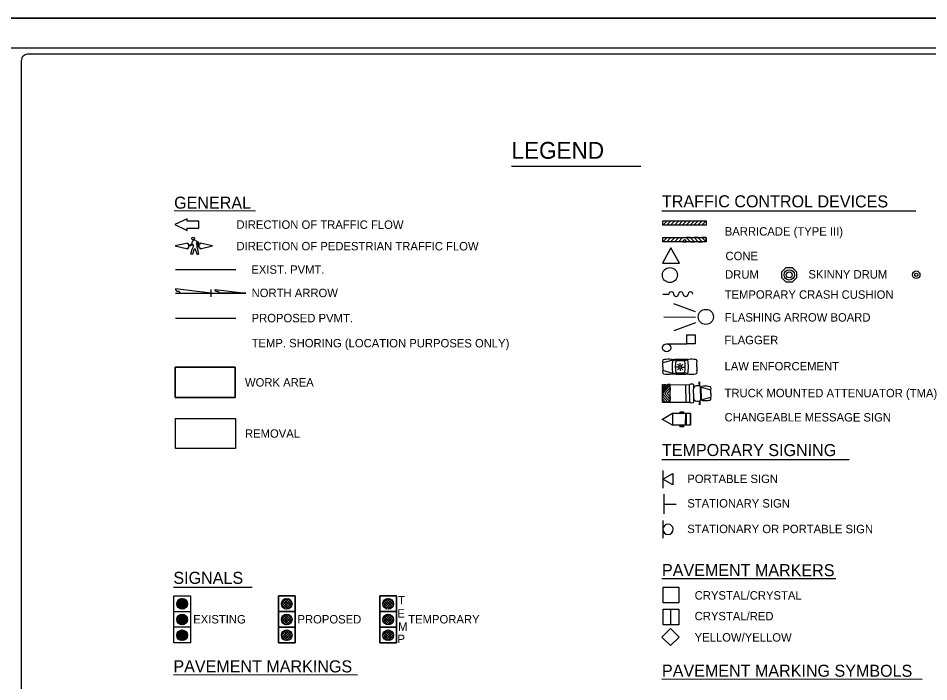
# Model space of a CAD drawing. Extents: x 198 to 2213, y -571 to 529.
# Drawn here: x 931 to 1688, y -22 to 529 of the extents above; entities that cross this region are included whole.
import ezdxf

# ---------------------------------------------------------------- set-up
doc = ezdxf.new("R2010")
doc.units = 0
for name, color, linetype in [('P_RDY_Dimension_Text', 7, 'Continuous'), ('Prop Shade Light', 7, 'Continuous'), ('Sheet Data Field CELL', 7, 'Continuous'), ('Sheet PE Seal CELL', 7, 'Continuous'), ('Sheet_Title_Block_Text', 7, 'Continuous'), ('Text', 7, 'Continuous')]:
    doc.layers.add(name, color=color, linetype=linetype)

msp = doc.modelspace()

# ---------------------------------------------------------------- linework, layer by layer
at = {"layer": 'P_RDY_Dimension_Text'}
for points in [[(1061.06, 214.03), (1111.06, 214.03), (1111.06, 239.03), (1061.06, 239.03)], [(1146.95, 49.25), (1160.75, 49.25), (1160.75, 9.95), (1146.95, 9.95)], [(1231.3, 49.25), (1245.1, 49.25), (1245.1, 9.95), (1231.3, 9.95)]]:
    msp.add_lwpolyline(points, close=True, dxfattribs=at)
at = {"layer": 'Prop Shade Light'}
for p, q in [((1072.69, 340.35), (1075.18, 341.98)), ((1075.18, 341.98), (1075.34, 342.96)), ((1076.14, 341.27), (1075.36, 340.55)), ((1077.97, 344.5), (1080.47, 343.01)), ((1079.56, 342.36), (1078.75, 342.52)), ((1079.78, 339.54), (1079.56, 342.36)), ((1080.47, 343.01), (1080.5, 339.54)), ((1073.08, 339.8), (1072.69, 340.35)), ((1075.36, 340.55), (1073.08, 339.8)), ((1074.18, 333.09), (1075.25, 337.14)), ((1075.51, 332.67), (1074.18, 333.09)), ((1075.25, 337.14), (1076.48, 339.41)), ((1076.67, 336.59), (1075.51, 332.67)), ((1077.65, 337.56), (1076.67, 336.59)), ((1079.62, 332.38), (1077.65, 337.56)), ((1079.31, 338.46), (1080.59, 333.06)), ((1080.59, 333.06), (1079.62, 332.38)), ((1080.5, 339.54), (1079.78, 339.54))]:
    msp.add_line(p, q, dxfattribs=at)
for centre, radius, start, end in [((1078.51, 342.44), 3.22, 140.16781, 170.55558), ((1076.69, 343.96), 0.84, 96.88059, 140.16781), ((1071.07, 339.38), 5.41, 0.28805, 20.36723), ((1076.85, 342.62), 2.19, 59.1458, 96.8806), ((1071.07, 339.38), 8.29, 353.63563, 22.23387)]:
    msp.add_arc(centre, radius, start, end, dxfattribs=at)
at = {"layer": 'Sheet Data Field CELL'}
for points in [[(197.66, -570.86), (1885.65, -570.86), (1885.65, 529.13), (197.66, 529.13)], [(197.66, 529.13), (1885.65, 529.13), (1885.65, -570.86), (197.66, -570.86)]]:
    msp.add_lwpolyline(points, close=True, dxfattribs=at)
at = {"layer": 'Sheet PE Seal CELL'}
for p, q in [((1850.37, 504.14), (370.94, 504.14)), ((933.13, 493.85), (933.13, -535.58)), ((1850.37, 499.14), (938.42, 499.14)), ((1340.7, 406.25), (1448.09, 406.18)), ((1060.26, 369.22), (1127.86, 369.17)), ((1465.78, 369.17), (1676.67, 369.02)), ((1071.18, 362.49), (1060.84, 357.63)), ((1060.84, 357.63), (1071.18, 352.75)), ((1071.18, 360.52), (1071.18, 362.49)), ((1080.78, 360.51), (1071.18, 360.52)), ((1080.78, 354.71), (1080.78, 360.51)), ((1466.45, 357.11), (1466.45, 360.71)), ((1466.45, 360.71), (1469.99, 360.71)), ((1469.99, 360.71), (1466.45, 357.11)), ((1466.45, 360.71), (1502.43, 360.71)), ((1466.45, 357.17), (1466.45, 360.71)), ((1502.43, 357.17), (1466.45, 357.17)), ((1469.69, 357.11), (1473.23, 360.71)), ((1472.92, 357.11), (1469.69, 357.11)), ((1476.47, 360.71), (1472.92, 357.11)), ((1473.23, 360.71), (1476.47, 360.71)), ((1476.16, 357.11), (1479.71, 360.71)), ((1479.4, 357.11), (1476.16, 357.11)), ((1482.94, 360.71), (1479.4, 357.11)), ((1479.71, 360.71), (1482.94, 360.71)), ((1482.64, 357.11), (1486.18, 360.71)), ((1485.88, 357.11), (1482.64, 357.11)), ((1489.42, 360.71), (1485.88, 357.11)), ((1486.18, 360.71), (1489.42, 360.71)), ((1489.11, 357.11), (1492.72, 360.71)), ((1492.35, 357.11), (1489.11, 357.11)), ((1495.95, 360.71), (1492.35, 357.11)), ((1492.72, 360.71), (1495.95, 360.71)), ((1495.59, 357.11), (1499.19, 360.71)), ((1498.83, 357.11), (1495.59, 357.11)), ((1502.43, 360.71), (1498.83, 357.11)), ((1499.19, 360.71), (1502.43, 360.71)), ((1502.43, 360.71), (1502.43, 357.17)), ((1071.18, 352.75), (1071.18, 354.72)), ((1071.18, 354.72), (1080.78, 354.71)), ((1071.52, 342.32), (1061.17, 339.89)), ((1071.51, 341.33), (1071.52, 342.32)), ((1072.44, 341.33), (1071.51, 341.33)), ((1072.44, 338.43), (1072.44, 341.33)), ((1081.79, 341.33), (1080.86, 341.33)), ((1080.86, 341.33), (1080.86, 338.43)), ((1092.13, 339.87), (1081.79, 342.31)), ((1081.79, 342.31), (1081.79, 341.33)), ((1466.46, 343.4), (1466.46, 347)), ((1466.46, 347), (1470, 347)), ((1470, 347), (1466.46, 343.4)), ((1466.46, 347), (1502.43, 347)), ((1466.46, 343.4), (1466.46, 347)), ((1502.43, 343.4), (1466.46, 343.4)), ((1469.69, 343.4), (1473.24, 347)), ((1472.93, 343.4), (1469.69, 343.4)), ((1476.47, 347), (1472.93, 343.4)), ((1473.24, 347), (1476.47, 347)), ((1476.17, 343.4), (1479.71, 347)), ((1479.4, 343.4), (1476.17, 343.4)), ((1482.95, 347), (1479.4, 343.4)), ((1479.71, 347), (1482.95, 347)), ((1482.64, 343.4), (1484.44, 345.23)), ((1485.88, 343.4), (1482.64, 343.4)), ((1483.01, 343.4), (1486.24, 343.4)), ((1484.44, 345.23), (1486.24, 343.4)), ((1489.18, 347), (1485.94, 347)), ((1485.94, 347), (1489.48, 343.4)), ((1492.72, 343.4), (1489.18, 347)), ((1489.48, 343.4), (1492.72, 343.4)), ((1495.65, 347), (1492.41, 347)), ((1492.41, 347), (1495.96, 343.4)), ((1499.19, 343.4), (1495.65, 347)), ((1495.96, 343.4), (1499.19, 343.4)), ((1502.43, 347), (1498.89, 347)), ((1498.89, 347), (1502.43, 343.4)), ((1502.43, 347), (1502.43, 343.4)), ((1502.43, 343.4), (1502.43, 347)), ((1061.17, 339.89), (1071.51, 337.45)), ((1071.51, 337.45), (1071.51, 338.43)), ((1071.51, 338.43), (1072.44, 338.43)), ((1080.86, 338.43), (1081.79, 338.43)), ((1081.79, 337.44), (1092.13, 339.87)), ((1081.79, 338.43), (1081.79, 337.44)), ((1061.47, 320.32), (1111.67, 320.29)), ((1090.7, 300.62), (1061.48, 304.21)), ((1090.7, 303.75), (1090.7, 297.49)), ((1094.42, 303.75), (1119.92, 300.62)), ((1061.48, 300.62), (1119.92, 300.62)), ((1064.93, 300.63), (1090.7, 300.62)), ((1119.92, 300.62), (1097.73, 300.62)), ((1466.5, 299.89), (1471.5, 299.89)), ((1493.75, 285.17), (1475.71, 291.75)), ((1493.75, 280.56), (1467.2, 280.58)), ((1061.47, 280.01), (1111.66, 279.97)), ((1493.74, 275.95), (1475.69, 269.4)), ((1469.67, 258.67), (1486.35, 258.66)), ((1474.76, 244.96), (1466.54, 242.71)), ((1466.54, 239.5), (1466.54, 242.71)), ((1474.76, 244.96), (1477.3, 244.41)), ((1480.9, 240.58), (1480.9, 242.6)), ((1487.18, 244.95), (1484.63, 244.4)), ((1486.45, 245.1), (1486.45, 244.79)), ((1494.64, 239.48), (1494.64, 242.69)), ((1466.54, 239.5), (1466.53, 236.27)), ((1474.75, 234.02), (1466.53, 236.27)), ((1479.6, 239.29), (1477.58, 239.3)), ((1479.98, 240.21), (1478.55, 241.63)), ((1479.97, 238.38), (1478.55, 236.95)), ((1480.89, 238), (1480.89, 235.98)), ((1481.8, 238.37), (1483.23, 236.94)), ((1481.81, 240.2), (1483.24, 241.63)), ((1482.19, 239.28), (1484.2, 239.28)), ((1494.64, 239.48), (1494.64, 236.25)), ((1474.75, 234.02), (1477.3, 234.57)), ((1487.17, 234.01), (1484.63, 234.56)), ((1486.44, 234.18), (1486.44, 233.88)), ((1486.44, 234.18), (1486.44, 233.88)), ((1466.16, 210.07), (1466.17, 224.62)), ((1472.62, 224.62), (1466.16, 217.35)), ((1466.16, 217.35), (1466.17, 219.6)), ((1466.17, 224.62), (1488.67, 224.6)), ((1466.17, 224.62), (1466.17, 221.84)), ((1466.17, 224.62), (1468.64, 224.62)), ((1468.64, 224.62), (1466.17, 221.84)), ((1466.17, 219.6), (1470.67, 224.62)), ((1468.19, 217.34), (1472.62, 222.37)), ((1472.62, 220.12), (1470.14, 217.34)), ((1470.67, 224.62), (1472.62, 224.62)), ((1472.61, 210.07), (1472.62, 224.62)), ((1472.62, 222.37), (1472.62, 220.12)), ((1485.59, 217.33), (1485.59, 224.61)), ((1488.66, 217.33), (1488.67, 224.6)), ((1492.11, 217.33), (1492.12, 224.6)), ((1496.77, 225.05), (1496.77, 226.85)), ((1497.07, 223.32), (1497.07, 226.85)), ((1497.29, 223.32), (1497.3, 226.85)), ((1497.89, 217.32), (1497.89, 222.57)), ((1498.41, 217.32), (1498.42, 222.57)), ((1498.42, 222.57), (1506.29, 220.39)), ((1506.29, 217.32), (1506.29, 220.39)), ((1466.16, 217.35), (1472.61, 210.07)), ((1466.16, 215.17), (1466.16, 217.35)), ((1470.66, 210.07), (1466.16, 215.17)), ((1466.16, 212.85), (1466.16, 210.07)), ((1468.63, 210.07), (1466.16, 212.85)), ((1472.61, 212.39), (1468.19, 217.34)), ((1470.21, 217.34), (1472.61, 214.64)), ((1472.61, 214.64), (1472.61, 212.39)), ((1485.59, 217.33), (1485.58, 210.06)), ((1488.66, 217.33), (1488.66, 210.05)), ((1492.11, 217.33), (1492.11, 210.05)), ((1497.89, 217.32), (1497.89, 212.07)), ((1498.41, 217.32), (1498.41, 212.07)), ((1498.41, 212.07), (1506.29, 214.24)), ((1506.29, 217.32), (1506.29, 214.24)), ((1466.16, 210.07), (1488.66, 210.05)), ((1466.16, 210.07), (1468.63, 210.07)), ((1472.61, 210.07), (1470.66, 210.07)), ((1496.76, 209.6), (1496.76, 207.87)), ((1497.06, 211.32), (1497.06, 207.87)), ((1497.29, 211.32), (1497.28, 207.87)), ((1474.48, 200.61), (1466.07, 195.76)), ((1474.48, 200.61), (1474.47, 190.91)), ((1489.5, 200.6), (1474.48, 200.61)), ((1483.83, 201.68), (1480.73, 201.68)), ((1483.83, 200.8), (1480.73, 200.8)), ((1485.19, 200.61), (1485.18, 190.9)), ((1485.99, 200.61), (1485.99, 190.9)), ((1489.5, 200.61), (1489.5, 190.9)), ((1489.5, 190.89), (1489.5, 200.6)), ((1474.47, 190.91), (1466.07, 195.76)), ((1489.5, 190.9), (1474.47, 190.91)), ((1483.82, 190.59), (1480.72, 190.6)), ((1483.82, 189.67), (1480.72, 189.68)), ((1465.78, 162.49), (1621.46, 162.38)), ((1466.57, 153.39), (1466.56, 138.54)), ((1466.56, 146.11), (1474.67, 150.76)), ((1474.66, 141.46), (1466.56, 146.11)), ((1474.67, 150.76), (1474.66, 141.46)), ((1467.19, 133.53), (1467.18, 117.33)), ((1467.18, 125.36), (1477.68, 125.35)), ((1466.56, 111.78), (1466.55, 96.93)), ((1465.78, 63.61), (1610.16, 63.51)), ((1059.64, 56.26), (1125.23, 56.21)), ((1149.45, 42.65), (1153.75, 46.95)), ((1149.8, 40.85), (1155.55, 46.65)), ((1150.6, 39.55), (1156.85, 45.8)), ((1157.5, 40.05), (1151.35, 46.2)), ((1158.15, 41.5), (1152.8, 46.85)), ((1158.1, 43.65), (1155, 46.8)), ((1233.8, 42.65), (1238.1, 46.95)), ((1234.15, 40.85), (1239.9, 46.65)), ((1234.95, 39.55), (1241.2, 45.8)), ((1241.85, 40.05), (1235.7, 46.2)), ((1242.5, 41.5), (1237.15, 46.85)), ((1242.45, 43.65), (1239.35, 46.8)), ((1152.95, 38.2), (1149.55, 41.65)), ((1155, 38.3), (1149.6, 43.7)), ((1156.45, 39), (1150.3, 45.1)), ((1151.8, 38.65), (1157.75, 44.55)), ((1153.45, 38.2), (1158.25, 42.95)), ((1156.35, 38.95), (1157.6, 40.2)), ((1237.3, 38.2), (1233.9, 41.65)), ((1239.35, 38.3), (1233.95, 43.7)), ((1240.8, 39), (1234.65, 45.1)), ((1236.15, 38.65), (1242.1, 44.55)), ((1237.8, 38.2), (1242.6, 42.95)), ((1240.7, 38.95), (1241.95, 40.2)), ((1149.45, 29.55), (1153.75, 33.85)), ((1155, 25.2), (1149.6, 30.6)), ((1149.8, 27.75), (1155.55, 33.55)), ((1156.45, 25.9), (1150.3, 32)), ((1150.6, 26.45), (1156.85, 32.7)), ((1157.5, 26.95), (1151.35, 33.1)), ((1151.8, 25.55), (1157.75, 31.45)), ((1158.15, 28.4), (1152.8, 33.75)), ((1158.1, 30.55), (1155, 33.7)), ((1233.8, 29.55), (1238.1, 33.85)), ((1239.35, 25.2), (1233.95, 30.6)), ((1234.15, 27.75), (1239.9, 33.55)), ((1240.8, 25.9), (1234.65, 32)), ((1234.95, 26.45), (1241.2, 32.7)), ((1241.85, 26.95), (1235.7, 33.1)), ((1236.15, 25.55), (1242.1, 31.45)), ((1242.5, 28.4), (1237.15, 33.75)), ((1242.45, 30.55), (1239.35, 33.7)), ((1152.95, 25.1), (1149.55, 28.55)), ((1153.45, 25.1), (1158.25, 29.85)), ((1156.35, 25.85), (1157.6, 27.1)), ((1237.3, 25.1), (1233.9, 28.55)), ((1237.8, 25.1), (1242.6, 29.85)), ((1240.7, 25.85), (1241.95, 27.1)), ((1149.45, 16.45), (1153.75, 20.75)), ((1152.95, 12), (1149.55, 15.45)), ((1155, 12.1), (1149.6, 17.5)), ((1149.8, 14.65), (1155.55, 20.45)), ((1156.45, 12.8), (1150.3, 18.9)), ((1150.6, 13.35), (1156.85, 19.6)), ((1157.5, 13.85), (1151.35, 20)), ((1151.8, 12.45), (1157.75, 18.35)), ((1158.15, 15.3), (1152.8, 20.65)), ((1153.45, 12), (1158.25, 16.75)), ((1158.1, 17.45), (1155, 20.6)), ((1233.8, 16.45), (1238.1, 20.75)), ((1237.3, 12), (1233.9, 15.45)), ((1239.35, 12.1), (1233.95, 17.5)), ((1234.15, 14.65), (1239.9, 20.45)), ((1240.8, 12.8), (1234.65, 18.9)), ((1234.95, 13.35), (1241.2, 19.6)), ((1241.85, 13.85), (1235.7, 20)), ((1236.15, 12.45), (1242.1, 18.35)), ((1242.5, 15.3), (1237.15, 20.65)), ((1237.8, 12), (1242.6, 16.75)), ((1242.45, 17.45), (1239.35, 20.6)), ((1156.35, 12.75), (1157.6, 14)), ((1240.7, 12.75), (1241.95, 14)), ((1059.64, -16.29), (1212.69, -16.4)), ((1465.78, -19.92), (1681.97, -20.08))]:
    msp.add_line(p, q, dxfattribs=at)
for points in [[(1473.2, 338.44), (1466.21, 325.48), (1480.3, 325.53)], [(1565.54, 313.37), (1565.54, 318.35), (1569.06, 321.88), (1574.04, 321.86), (1577.55, 318.34), (1577.55, 313.36), (1574.03, 309.83), (1569.05, 309.85)], [(1486.35, 258.66), (1486.36, 265.92), (1493.32, 265.91), (1493.31, 258.65)], [(1111.06, 239.03), (1061.06, 239.03), (1061.06, 214.03), (1111.06, 214.03)], [(1061.06, 239.03), (1111.06, 239.03), (1111.06, 214.03), (1061.06, 214.03)], [(1470.67, 224.62), (1466.17, 219.6), (1466.16, 215.17), (1470.66, 210.07), (1472.61, 210.07), (1466.16, 217.35), (1472.62, 224.62)], [(1466.17, 221.84), (1466.17, 224.62), (1468.64, 224.62)], [(1472.61, 212.39), (1468.19, 217.34), (1472.62, 222.37), (1472.62, 220.12), (1470.21, 217.34), (1472.61, 214.64)], [(1466.16, 212.85), (1468.63, 210.07), (1466.16, 210.07)], [(1061.28, 196.52), (1111.28, 196.52), (1111.28, 171.52), (1061.28, 171.52)], [(1061.28, 196.52), (1111.28, 196.52), (1111.28, 171.52), (1061.28, 171.52)], [(1061.28, 196.52), (1111.28, 196.52), (1111.28, 171.52), (1061.28, 171.52)], [(1146.95, 36.15), (1160.75, 36.15), (1160.75, 49.25), (1146.95, 49.25)], [(1231.3, 36.15), (1245.1, 36.15), (1245.1, 49.25), (1231.3, 49.25)], [(1473.14, 38.15), (1479.65, 38.15), (1479.65, 25.15), (1473.14, 25.15)], [(1146.95, 23.05), (1160.75, 23.05), (1160.75, 36.15), (1146.95, 36.15)], [(1231.3, 23.05), (1245.1, 23.05), (1245.1, 36.15), (1231.3, 36.15)], [(1146.95, 9.95), (1160.75, 9.95), (1160.75, 23.05), (1146.95, 23.05)], [(1231.3, 9.95), (1245.1, 9.95), (1245.1, 23.05), (1231.3, 23.05)], [(1472.85, 7.76), (1465.74, 14.87), (1472.85, 21.99), (1479.96, 14.87)]]:
    msp.add_lwpolyline(points, close=True, dxfattribs=at)
for points in [[(1466.81, 56.28), (1479.81, 56.28), (1479.81, 43.28), (1466.81, 43.28), (1466.81, 56.28)], [(1466.65, 38.15), (1479.65, 38.15), (1479.65, 25.15), (1466.65, 25.15), (1466.65, 38.15)]]:
    msp.add_lwpolyline(points, dxfattribs=at)
for centre, radius in [((1076.03, 346.09), 1.11), ((1472.35, 315.7), 6.25), ((1571.55, 315.85), 4.31), ((1571.55, 315.85), 2.5), ((1677.11, 315.96), 3.13), ((1677.11, 315.96), 1.33), ((1502.24, 280.97), 6.25), ((1469.67, 255.28), 3.37), ((1480.89, 239.29), 1.01), ((1465.99, 195.77), 0.0857), ((1153.85, 42.55), 4.44), ((1238.2, 42.55), 4.44), ((1153.85, 29.45), 4.44), ((1238.2, 29.45), 4.44), ((1153.85, 16.35), 4.44), ((1238.2, 16.35), 4.44)]:
    msp.add_circle(centre, radius, dxfattribs=at)
for centre, radius, start, end in [((938.42, 493.85), 5.29, 89.99715, 180), ((1473.5, 299.88), 2, 359.9598, 179.9598), ((1477.5, 299.88), 2, 179.9598, 359.9598), ((1481.5, 299.88), 2, 359.9598, 179.9598), ((1485.5, 299.87), 2, 179.9598, 359.9598), ((1489.5, 299.87), 2, 359.9598, 179.9598), ((1468.57, 243.78), 2.28, 151.83987, 208.07972), ((1500.12, 239.47), 25.94, 167.79219, 192.12741), ((1481.8, 181.95), 63.71, 85.11271, 96.5547), ((1500.12, 239.47), 23.34, 167.79219, 192.12741), ((1480.93, 193.04), 51.49, 85.87776, 94.04184), ((1461.82, 239.5), 23.34, 347.79219, 12.12741), ((1461.82, 239.5), 25.94, 347.79219, 12.12741), ((1492.62, 243.76), 2.28, 331.83988, 28.07973), ((1468.56, 235.2), 2.28, 151.83987, 208.07972), ((1492.62, 235.18), 2.28, 331.83988, 28.07973), ((1481.88, 297.04), 63.71, 263.3649, 274.69733), ((1481, 288.33), 53.89, 266.05981, 273.85979), ((1504.35, 221.44), 2.18, 331.83987, 28.07972), ((1504.34, 213.21), 2.18, 331.83987, 28.07973), ((1481.3, 201.24), 0.716, 142.04815, 217.87145), ((1483.27, 201.24), 0.716, 322.04815, 37.87145), ((1481.29, 190.15), 0.716, 142.04815, 217.87145), ((1483.26, 190.15), 0.716, 322.04815, 37.87145), ((1470.83, 104.36), 4.28, 182.94264, 179.77584)]:
    msp.add_arc(centre, radius, start, end, dxfattribs=at)
for centre, major_axis, ratio, start_param, end_param in [((1470.66, 244.9), (-4.1, -0.04), 0.2034, 3.141593, 6.283185), ((1490.53, 244.88), (4.1, -0.05), 0.2034, 0, 2.945373), ((1470.65, 234.08), (-4.1, 0.05), 0.2034, 0, 3.141593), ((1490.52, 234.06), (4.1, 0.04), 0.2034, 3.331712, 6.283185), ((1490.42, 224.61), (1.73, 0), 0.269913, 0, 3.141593), ((1495.03, 222.22), (2.89, 0.36), 0.503092, 0, 3.141593), ((1502.34, 222.52), (3.94, -0.05), 0.2034, 0, 3.141593), ((1495.03, 212.45), (2.89, -0.36), 0.503092, 3.141593, 6.283185), ((1502.33, 212.14), (3.94, 0.04), 0.2034, 3.141593, 6.283185), ((1490.41, 210.07), (1.73, 0), 0.269913, 3.141593, 6.283185)]:
    msp.add_ellipse(centre, major_axis=major_axis, ratio=ratio, start_param=start_param, end_param=end_param, dxfattribs=at)
for points in [[(1061.48, 304.21), (1061.39, 302.39), (1064.96, 302.33), (1064.93, 300.63)], [(1097.73, 300.62), (1097.9, 301.88), (1094.33, 301.94), (1094.42, 303.75)]]:
    msp.add_open_spline(points, degree=2, dxfattribs=at)
at = {"layer": 'Sheet_Title_Block_Text'}
msp.add_lwpolyline([(1472.85, 7.76), (1479.96, 14.87), (1472.85, 21.99), (1465.74, 14.87)], close=True, dxfattribs=at)
msp.add_lwpolyline([(1472.85, 7.76), (1479.96, 14.87), (1472.85, 21.99), (1465.74, 14.87)], close=True, dxfattribs=at)
at = {"layer": 'Text'}
for p, q in [((1059.96, 49.25), (1073.76, 49.25)), ((1059.96, 36.15), (1059.96, 49.25)), ((1062.43, 42.86), (1066.54, 46.97)), ((1062.53, 41.55), (1067.85, 46.87)), ((1062.91, 40.52), (1068.89, 46.49)), ((1063.17, 45.02), (1064.38, 46.23)), ((1063.48, 39.67), (1069.73, 45.93)), ((1063.54, 45.49), (1069.8, 39.23)), ((1064.28, 46.16), (1070.47, 39.97)), ((1065.19, 46.66), (1070.97, 40.89)), ((1066.32, 46.95), (1071.26, 42.01)), ((1067.8, 46.88), (1071.19, 43.49)), ((1073.76, 49.25), (1073.76, 36.15)), ((1062.42, 42.36), (1066.67, 38.11)), ((1062.56, 43.64), (1067.95, 38.25)), ((1062.95, 44.66), (1068.97, 38.65)), ((1062.97, 40.4), (1064.71, 38.67)), ((1064.21, 38.99), (1070.42, 45.2)), ((1065.11, 38.47), (1070.93, 44.3)), ((1066.21, 38.16), (1071.25, 43.2)), ((1067.64, 38.18), (1071.22, 41.76)), ((1059.96, 36.15), (1073.76, 36.15)), ((1059.96, 23.05), (1059.96, 36.15)), ((1062.42, 29.49), (1066.81, 33.89)), ((1062.58, 28.24), (1068.06, 33.72)), ((1062.63, 30.79), (1068.2, 25.22)), ((1062.83, 31.32), (1064.99, 33.47)), ((1063, 27.25), (1069.06, 33.3)), ((1063.07, 31.76), (1069.17, 25.66)), ((1063.6, 26.43), (1069.87, 32.7)), ((1063.69, 32.56), (1069.97, 26.28)), ((1064.36, 25.78), (1070.53, 31.94)), ((1064.47, 33.19), (1070.6, 27.06)), ((1065.29, 25.29), (1071.01, 31.01)), ((1065.43, 33.65), (1071.06, 28.02)), ((1066.61, 33.88), (1071.29, 29.21)), ((1068.24, 33.66), (1071.07, 30.84)), ((1073.76, 36.15), (1073.76, 23.05)), ((1073.76, 23.05), (1059.96, 23.05)), ((1059.96, 9.95), (1059.96, 23.05)), ((1062.42, 29.59), (1066.99, 25.01)), ((1062.7, 27.89), (1065.3, 25.29)), ((1066.44, 25.03), (1071.27, 29.86)), ((1067.98, 25.16), (1071.15, 28.32)), ((1073.76, 23.05), (1073.76, 9.95)), ((1062.43, 16.69), (1067.19, 11.92)), ((1062.45, 16.85), (1066.35, 20.76)), ((1062.5, 15.49), (1067.71, 20.7)), ((1062.68, 17.85), (1068.36, 12.17)), ((1062.85, 14.43), (1068.77, 20.35)), ((1063.15, 18.79), (1069.3, 12.64)), ((1063.4, 13.56), (1069.64, 19.8)), ((1063.8, 19.56), (1070.07, 13.29)), ((1064.11, 12.86), (1070.34, 19.09)), ((1064.6, 20.17), (1070.68, 14.1)), ((1064.99, 12.32), (1070.88, 18.21)), ((1065.59, 20.6), (1071.11, 15.08)), ((1066.06, 11.98), (1071.22, 17.14)), ((1066.82, 20.79), (1071.29, 16.31)), ((1067.44, 11.95), (1071.25, 15.76)), ((1068.58, 20.44), (1070.94, 18.07)), ((1073.76, 9.95), (1059.96, 9.95)), ((1062.59, 15.11), (1065.62, 12.09))]:
    msp.add_line(p, q, dxfattribs=at)
for centre in [(1066.86, 42.55), (1066.86, 29.45), (1066.86, 16.35)]:
    msp.add_circle(centre, 4.44, dxfattribs=at)

# ---------------------------------------------------------------- texts
at = {"layer": 'Sheet PE Seal CELL'}
for s, height, rotation, p in [('LEGEND', 13.999, 359.9598, (1340.67, 412.34)), ('GENERAL', 10, 359.9598, (1060.26, 370.87)), ('TRAFFIC CONTROL DEVICES', 10, 359.9598, (1465.78, 372.03)), ('DIRECTION OF TRAFFIC FLOW', 7, 359.9598, (1112.07, 354.17)), ('BARRICADE (TYPE III)', 7, 359.9598, (1517.96, 348.51)), ('DIRECTION OF PEDESTRIAN TRAFFIC FLOW', 7, 359.9598, (1112.07, 336.28)), ('CONE', 7, 359.9598, (1518.54, 328.07)), ('EXIST. PVMT.', 7, 359.9598, (1124.4, 316.79)), ('DRUM', 7, 359.9598, (1518.21, 312.71)), ('SKINNY DRUM', 7, 359.9598, (1587.53, 312.86)), ('NORTH ARROW', 7, 359.9598, (1124.64, 297.42)), ('TEMPORARY CRASH CUSHION', 7, 359.9598, (1517.83, 296.06)), ('PROPOSED PVMT.', 7, 359.9598, (1124.63, 276.47)), ('FLASHING ARROW BOARD', 7, 359.9598, (1517.92, 277.08)), ('FLAGGER', 7, 359.9598, (1517.76, 258.25)), ('TEMP. SHORING (LOCATION PURPOSES ONLY)', 7, 359.9598, (1124.63, 255.67)), ('LAW ENFORCEMENT', 7, 359.9598, (1517.77, 236.51)), ('WORK AREA', 7, 360, (1119.12, 223.03)), ('TRUCK MOUNTED ATTENUATOR (TMA)', 7, 359.9598, (1517.79, 214.2)), ('CHANGEABLE MESSAGE SIGN', 7, 359.9598, (1517.81, 194.08)), ('REMOVAL', 7, 360, (1119.12, 180.52)), ('TEMPORARY SIGNING', 10, 359.9598, (1465.78, 165.35)), ('PORTABLE SIGN', 7, 359.9598, (1486.78, 142.9)), ('STATIONARY SIGN', 7, 359.9598, (1486.8, 122.52)), ('STATIONARY OR PORTABLE SIGN', 7, 359.9598, (1486.77, 101.29)), ('SIGNALS', 10, 359.9598, (1059.64, 59.11)), ('PAVEMENT MARKERS', 10, 359.9598, (1465.78, 65.53)), ('CRYSTAL/CRYSTAL', 7, 359.9598, (1492.95, 46.05)), ('EXISTING', 7, 359.9598, (1076.11, 26.2)), ('PROPOSED', 7, 359.9598, (1162.76, 26.2)), ('TEMPORARY ', 7, 359.9598, (1254.85, 26.21)), ('CRYSTAL/RED', 7, 359.9598, (1492.93, 28.79)), ('YELLOW/YELLOW', 7, 359.9598, (1492.94, 11.14)), ('PAVEMENT MARKINGS', 10, 359.9598, (1059.64, -14.37)), ('PAVEMENT MARKING SYMBOLS', 10, 359.9598, (1465.78, -18))]:
    msp.add_text(s, height=height, rotation=rotation, dxfattribs=at).set_placement(p)
for s, p in [('T', (1246.35, 42.08)), ('T', (1246.35, 42.08)), ('E', (1245.87, 31.03)), ('E', (1245.87, 31.03)), ('M', (1246.42, 19.99)), ('M', (1246.42, 19.99)), ('P', (1245.93, 9.81)), ('P', (1245.93, 9.81))]:
    msp.add_text(s, height=7, dxfattribs=at).set_placement(p)

doc.saveas('drawing.dxf')
